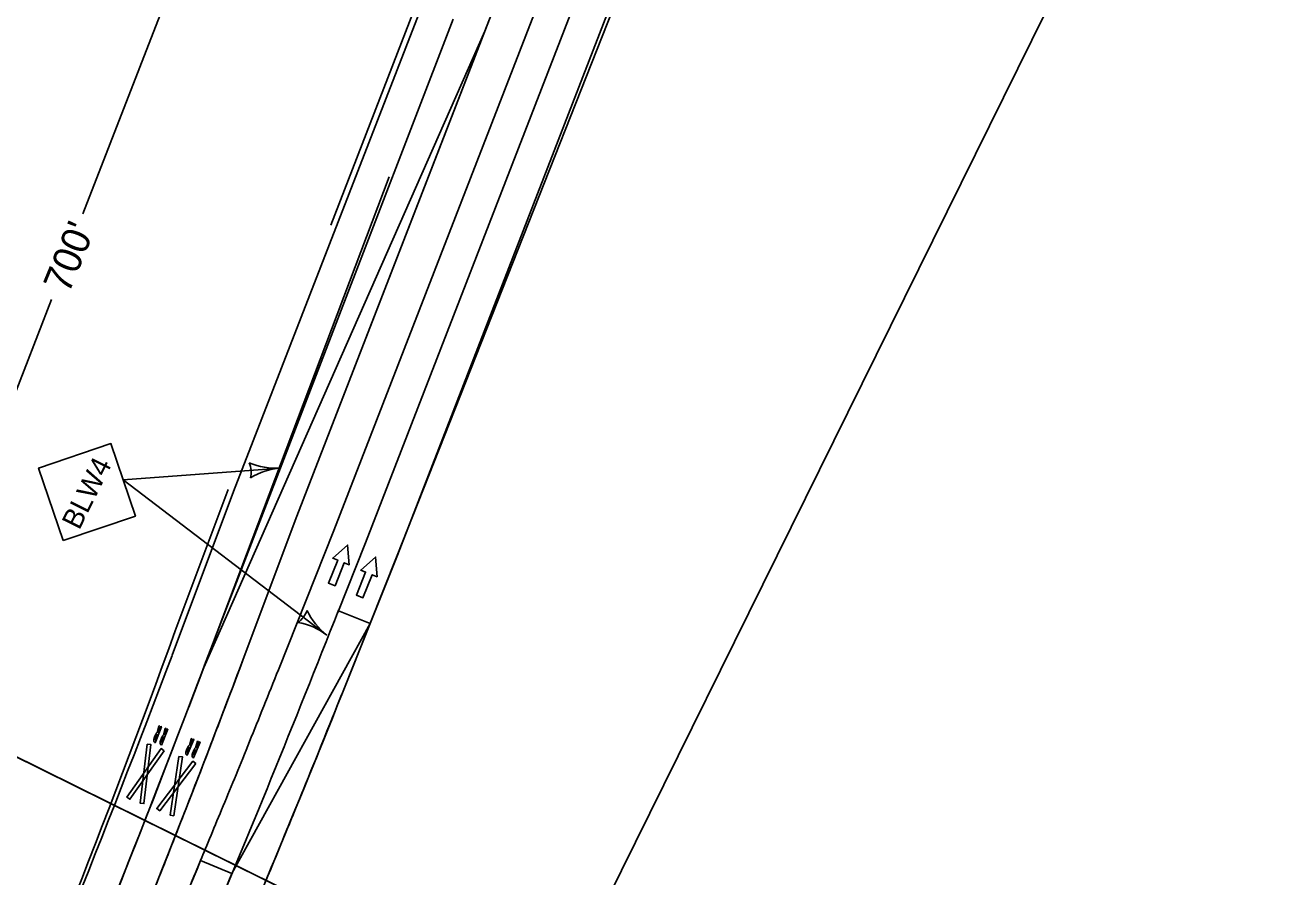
# Model space of a CAD drawing. Extents: x 14097936 to 14128734, y 8632000 to 8683104.
# Drawn here: x 14119789.7 to 14120235.7, y 8670080.4 to 8670380.8 of the extents above; entities that cross this region are included whole.
import ezdxf

# ---------------------------------------------------------------- set-up
doc = ezdxf.new("R2010")
doc.units = 0
for name, color, linetype in [('dsnNonPlotable', 7, 'Continuous'), ('dsnPaintExistingBrokenLaneLineWhite', 7, 'Continuous'), ('dsnPaintExistingEdgeLineRightWhite', 7, 'Continuous'), ('dsnPaintExistingNoPassingYellow', 7, 'Continuous'), ('dsnPaintPlaceBrokenLaneWhite', 7, 'Continuous'), ('dsnPaintPlaceNoPassingYellow', 7, 'Continuous'), ('dsnPaintRemoveChannelizingLaneYellow', 7, 'Continuous'), ('dsnShadingPaved', 7, 'Continuous'), ('dsnStdLabel', 7, 'Continuous'), ('dsnTapeRemoveChannelizingLaneWhite', 7, 'Continuous'), ('dsnTapeRemoveChannelizingLaneYellow', 7, 'Continuous'), ('Level 2', 7, 'Continuous'), ('Level 5', 7, 'Continuous'), ('trf_Cells1', 7, 'Continuous')]:
    doc.layers.add(name, color=color, linetype=linetype)

msp = doc.modelspace()

# ---------------------------------------------------------------- linework, layer by layer
at = {"layer": 'dsnNonPlotable'}
for points in [[(14119930.17, 8669941), (14120624.9, 8671346.14), (14120172.2, 8671569.96), (14119477.47, 8670164.82)], [(14118631.64, 8668945.1), (14119326.37, 8670350.23), (14120231.75, 8669902.59), (14119537.02, 8668497.46)], [(14119315.27, 8668607.09), (14120010, 8670012.23), (14119557.31, 8670236.05), (14118862.58, 8668830.91)]]:
    msp.add_lwpolyline(points, close=True, dxfattribs=at)
at = {"layer": 'dsnPaintExistingBrokenLaneLineWhite'}
for p, q in [((14119909.84, 8670198.21), (14120020.67, 8670484.12)), ((14119900.04, 8670173.67), (14119909.84, 8670198.21))]:
    msp.add_line(p, q, dxfattribs=at)
at = {"layer": 'dsnPaintExistingEdgeLineRightWhite'}
for p, q in [((14119972.19, 8670502.91), (14119897.54, 8670310.36)), ((14119920.98, 8670193.76), (14120033.72, 8670479.06)), ((14119861.35, 8670217.01), (14119842.61, 8670167.16)), ((14119901.38, 8670144.67), (14119920.98, 8670193.76))]:
    msp.add_line(p, q, dxfattribs=at)
for centre, radius, start, end in [((14116594.62, 8671342.65), 3454.16, 336.55764, 340.10427), ((14115455.27, 8671919.94), 4787.43, 334.8735, 338.23249)]:
    msp.add_arc(centre, radius, start, end, dxfattribs=at)
at = {"layer": 'dsnPaintExistingNoPassingYellow'}
for p, q in [((14119996.43, 8670493.52), (14119885.6, 8670207.61)), ((14119898.65, 8670202.55), (14120009.48, 8670488.46)), ((14119885.6, 8670207.61), (14119866.99, 8670158.14)), ((14119879.05, 8670153.47), (14119898.65, 8670202.55))]:
    msp.add_line(p, q, dxfattribs=at)
msp.add_arc((14115417.89, 8671831.2), 4753.27, 337.16763, 339.39146, dxfattribs=at)
at = {"layer": 'dsnPaintPlaceBrokenLaneWhite'}
msp.add_line((14119940.73, 8670383.04), (14119855.76, 8670162.36), dxfattribs=at)
for centre, radius, start, end in [((14115456.71, 8671919.32), 4773.86, 335.49481, 338.56158), ((14115416.69, 8671831.7), 4742.58, 334.09122, 339.391)]:
    msp.add_arc(centre, radius, start, end, dxfattribs=at)
at = {"layer": 'dsnPaintPlaceNoPassingYellow'}
msp.add_arc((14115456.71, 8671919.32), 4761.86, 334.13293, 337.35837, dxfattribs=at)
at = {"layer": 'dsnPaintRemoveChannelizingLaneYellow'}
msp.add_arc((14115570.48, 8671771.3), 4577.36, 336.80891, 339.3131, dxfattribs=at)
at = {"layer": 'dsnShadingPaved'}
for p, q in [((14119863.22, 8670216.29), (14119974.05, 8670502.19)), ((14119996.43, 8670493.52), (14119951.92, 8670378.71)), ((14119951.92, 8670378.71), (14119996.43, 8670493.52)), ((14119898.65, 8670202.55), (14120009.48, 8670488.46)), ((14120009.48, 8670488.46), (14119898.65, 8670202.55)), ((14119909.84, 8670198.21), (14120020.67, 8670484.12)), ((14120031.86, 8670479.78), (14119921.03, 8670193.88)), ((14119951.92, 8670378.71), (14119852.71, 8670154.3)), ((14119951.92, 8670378.71), (14119852.71, 8670154.3)), ((14119951.92, 8670378.71), (14119852.71, 8670154.3)), ((14119885.6, 8670207.61), (14119951.92, 8670378.71)), ((14119885.6, 8670207.61), (14119951.92, 8670378.71)), ((14119847.38, 8670140.26), (14119918.18, 8670327.31)), ((14119841.48, 8670158.54), (14119863.22, 8670216.29)), ((14119866.99, 8670158.14), (14119885.6, 8670207.61)), ((14119866.99, 8670158.14), (14119885.6, 8670207.61)), ((14119879.05, 8670153.47), (14119898.65, 8670202.55)), ((14119898.65, 8670202.55), (14119879.05, 8670153.47)), ((14119911.4, 8670169.76), (14119921.03, 8670193.88)), ((14119921.03, 8670193.88), (14119911.4, 8670169.76)), ((14119911.4, 8670169.76), (14119900.25, 8670174.21)), ((14119862.65, 8670081.54), (14119911.4, 8670169.76)), ((14119911.4, 8670169.76), (14119862.65, 8670081.54)), ((14119862.65, 8670081.54), (14119911.4, 8670169.76)), ((14119851.58, 8670086.16), (14119862.65, 8670081.54)), ((14119862.65, 8670081.54), (14119851.58, 8670086.16)), ((14119851.58, 8670086.16), (14119862.65, 8670081.54))]:
    msp.add_line(p, q, dxfattribs=at)
for points in [[(14119911.4, 8670169.76), (14119901.38, 8670144.67), (14119899.93, 8670141.07), (14119899.04, 8670138.84), (14119898.06, 8670136.41), (14119897.89, 8670135.99), (14119897.17, 8670134.2), (14119896.19, 8670131.75), (14119895.3, 8670129.55), (14119894.4, 8670127.31), (14119894.31, 8670127.08), (14119893.43, 8670124.9), (14119892.43, 8670122.42), (14119891.55, 8670120.26), (14119890.89, 8670118.63), (14119890.54, 8670117.75), (14119889.67, 8670115.61), (14119888.64, 8670113.09), (14119887.77, 8670110.96), (14119887.36, 8670109.96), (14119886.74, 8670108.43), (14119885.88, 8670106.32), (14119884.83, 8670103.77), (14119883.97, 8670101.68), (14119883.81, 8670101.29), (14119882.92, 8670099.11), (14119882.07, 8670097.05), (14119881, 8670094.46), (14119880.25, 8670092.64), (14119880.16, 8670092.41), (14119879.08, 8670089.81), (14119878.24, 8670087.78), (14119877.15, 8670085.17), (14119876.67, 8670084), (14119876.32, 8670083.15), (14119875.22, 8670080.52), (14119874.39, 8670078.53)], [(14119848.39, 8670078.55), (14119849.21, 8670080.5), (14119850.32, 8670083.15), (14119851.58, 8670086.16)], [(14119851.58, 8670086.16), (14119850.32, 8670083.15), (14119849.21, 8670080.5), (14119848.39, 8670078.55)]]:
    msp.add_lwpolyline(points, dxfattribs=at)
for radius, start in [(4565.36, 336.7987), (4577.36, 336.80891), (4577.36, 336.80891)]:
    msp.add_arc((14115570.48, 8671771.3), radius, start, 339.3131, dxfattribs=at)
for points in [[(14119789.07, 8669964), (14119790.92, 8669968.32), (14119796.39, 8669981.2), (14119805.42, 8670002.67), (14119816.06, 8670028.43), (14119826.56, 8670054.25), (14119836.9, 8670080.13), (14119847.09, 8670106.08), (14119857.14, 8670132.07), (14119863.71, 8670149.45), (14119866.99, 8670158.14)], [(14119789.07, 8669964), (14119790.92, 8669968.32), (14119796.39, 8669981.2), (14119805.42, 8670002.67), (14119816.06, 8670028.43), (14119826.56, 8670054.25), (14119836.9, 8670080.13), (14119847.09, 8670106.08), (14119857.14, 8670132.07), (14119863.71, 8670149.45), (14119866.99, 8670158.14)], [(14119851.58, 8670086.16), (14119853.73, 8670091.34), (14119859.45, 8670105.11), (14119868.64, 8670127.53), (14119875.58, 8670144.82), (14119879.05, 8670153.47)], [(14119879.05, 8670153.47), (14119875.58, 8670144.82), (14119868.64, 8670127.53), (14119859.45, 8670105.11), (14119853.73, 8670091.34), (14119851.58, 8670086.16)]]:
    msp.add_open_spline(points, degree=3, dxfattribs=at)
at = {"layer": 'dsnStdLabel'}
for p, q in [((14119810.02, 8670314.3), (14119929.02, 8670621.21)), ((14119765.11, 8670196.89), (14119798.91, 8670284.08)), ((14119879.73, 8670224.61), (14119824.26, 8670220.46)), ((14119896.13, 8670165.71), (14119824.26, 8670220.46))]:
    msp.add_line(p, q, dxfattribs=at)
msp.add_lwpolyline([(14119803.01, 8670199.02), (14119828.58, 8670207.67), (14119819.93, 8670233.25), (14119794.35, 8670224.6)], close=True, dxfattribs=at)
for centre, radius, start, end in [((14119878.02, 8670247.49), 22.95, 246.2011, 274.2724), ((14119860.54, 8670223.17), 8.86, 346.5381, 22.0066), ((14119881.44, 8670201.72), 22.95, 94.2723, 122.3435), ((14119880.83, 8670177.37), 8.86, 304.9652, 340.4336), ((14119910.04, 8670183.96), 22.95, 204.6282, 232.6995), ((14119882.23, 8670147.45), 22.95, 52.6993, 80.7706)]:
    msp.add_arc(centre, radius, start, end, dxfattribs=at)
at = {"layer": 'dsnTapeRemoveChannelizingLaneWhite'}
msp.add_line((14119862.65, 8670081.54), (14119911.4, 8670169.76), dxfattribs=at)
msp.add_arc((14118559.34, 8670625.19), 1412.15, 319.58068, 337.35767, dxfattribs=at)
at = {"layer": 'dsnTapeRemoveChannelizingLaneYellow'}
msp.add_line((14119951.92, 8670378.71), (14119852.71, 8670154.3), dxfattribs=at)
msp.add_arc((14118559.34, 8670625.19), 1400.15, 321.68516, 337.35766, dxfattribs=at)
at = {"layer": 'Level 2'}
for points in [[(14119896.72, 8670184), (14119899.04, 8670183.07), (14119902.29, 8670191.2), (14119904.03, 8670190.5), (14119903.46, 8670197.46), (14119898.23, 8670192.82), (14119899.97, 8670192.13)], [(14119906.58, 8670179.77), (14119908.9, 8670178.84), (14119912.16, 8670186.96), (14119913.9, 8670186.26), (14119913.32, 8670193.23), (14119908.1, 8670188.59), (14119909.84, 8670187.89)]]:
    msp.add_lwpolyline(points, close=True, dxfattribs=at)
at = {"layer": 'Level 5'}
for points in [[(14119899.97, 8670192.13), (14119898.23, 8670192.82), (14119903.46, 8670197.46), (14119904.03, 8670190.5), (14119902.29, 8670191.2), (14119899.04, 8670183.07), (14119896.72, 8670184), (14119899.97, 8670192.13)], [(14119909.84, 8670187.89), (14119908.1, 8670188.59), (14119913.32, 8670193.23), (14119913.9, 8670186.26), (14119912.16, 8670186.96), (14119908.9, 8670178.84), (14119906.58, 8670179.77), (14119909.84, 8670187.89)]]:
    msp.add_lwpolyline(points, dxfattribs=at)
at = {"layer": 'trf_Cells1'}
for p, q in [((14119835.46, 8670130.07), (14119835.29, 8670129.62)), ((14119835.7, 8670128.69), (14119836.39, 8670130.49)), ((14119837.7, 8670129.21), (14119837.53, 8670128.76)), ((14119837.94, 8670127.83), (14119838.63, 8670129.63)), ((14119846.8, 8670125.65), (14119846.61, 8670125.21)), ((14119847, 8670124.27), (14119847.75, 8670126.04)), ((14119849.01, 8670124.72), (14119848.82, 8670124.27)), ((14119849.21, 8670123.33), (14119849.96, 8670125.1))]:
    msp.add_line(p, q, dxfattribs=at)
for points in [[(14119836.46, 8670131.4), (14119837.06, 8670133.57), (14119836.84, 8670133.66), (14119836.21, 8670131.3)], [(14119835.58, 8670127.71), (14119837.73, 8670133.31), (14119837.51, 8670133.4), (14119836.73, 8670131.38)], [(14119837.82, 8670126.85), (14119839.97, 8670132.45), (14119839.75, 8670132.54), (14119838.97, 8670130.52)], [(14119838.7, 8670130.54), (14119839.3, 8670132.71), (14119839.08, 8670132.8), (14119838.45, 8670130.44)], [(14119847.85, 8670126.95), (14119848.52, 8670129.09), (14119848.3, 8670129.19), (14119847.6, 8670126.86)], [(14119846.84, 8670123.29), (14119849.19, 8670128.81), (14119848.97, 8670128.91), (14119848.12, 8670126.92)], [(14119849.05, 8670122.35), (14119851.4, 8670127.88), (14119851.17, 8670127.97), (14119850.33, 8670125.98)], [(14119850.06, 8670126.01), (14119850.73, 8670128.16), (14119850.51, 8670128.25), (14119849.8, 8670125.92)]]:
    msp.add_lwpolyline(points, dxfattribs=at)
for points in [[(14119838.75, 8670124.89), (14119826.6, 8670107.77), (14119825.52, 8670108.55), (14119837.66, 8670125.66)], [(14119832.68, 8670127.22), (14119830.26, 8670106.37), (14119831.58, 8670106.22), (14119834.01, 8670127.06)], [(14119849.91, 8670120.36), (14119837.17, 8670103.68), (14119836.11, 8670104.49), (14119848.85, 8670121.17)], [(14119843.93, 8670122.9), (14119840.78, 8670102.15), (14119842.1, 8670101.95), (14119845.24, 8670122.7)]]:
    msp.add_lwpolyline(points, close=True, dxfattribs=at)
for points in [[(14119835.29, 8670129.62), (14119835.15, 8670129.25), (14119835.11, 8670129.07), (14119835.08, 8670128.92), (14119835.06, 8670128.77), (14119835.05, 8670128.65), (14119835.05, 8670128.48), (14119835.06, 8670128.37), (14119835.08, 8670128.27), (14119835.1, 8670128.19), (14119835.14, 8670128.08), (14119835.17, 8670128.02), (14119835.22, 8670127.96), (14119835.26, 8670127.91), (14119835.32, 8670127.85), (14119835.37, 8670127.82), (14119835.44, 8670127.78), (14119835.58, 8670127.71)], [(14119835.6, 8670129.76), (14119835.55, 8670129.64), (14119835.51, 8670129.52), (14119835.48, 8670129.41), (14119835.45, 8670129.26), (14119835.45, 8670129.18), (14119835.44, 8670129.09), (14119835.45, 8670129.02), (14119835.46, 8670128.96), (14119835.49, 8670128.89), (14119835.53, 8670128.83), (14119835.57, 8670128.78), (14119835.63, 8670128.74), (14119835.7, 8670128.69)], [(14119836.21, 8670131.3), (14119836.17, 8670131.28), (14119836.09, 8670131.21), (14119836, 8670131.11), (14119835.95, 8670131.04), (14119835.88, 8670130.93), (14119835.81, 8670130.82), (14119835.77, 8670130.75), (14119835.71, 8670130.63), (14119835.64, 8670130.5), (14119835.6, 8670130.41), (14119835.55, 8670130.29), (14119835.46, 8670130.07)], [(14119836.39, 8670130.49), (14119836.31, 8670130.5), (14119836.24, 8670130.51), (14119836.17, 8670130.5), (14119836.1, 8670130.48), (14119836.04, 8670130.45), (14119835.98, 8670130.41), (14119835.93, 8670130.36), (14119835.87, 8670130.29), (14119835.83, 8670130.23), (14119835.75, 8670130.1), (14119835.69, 8670129.99), (14119835.65, 8670129.89), (14119835.6, 8670129.76)], [(14119836.73, 8670131.38), (14119836.64, 8670131.4), (14119836.53, 8670131.41), (14119836.46, 8670131.4)], [(14119838.45, 8670130.44), (14119838.41, 8670130.42), (14119838.33, 8670130.35), (14119838.24, 8670130.25), (14119838.19, 8670130.18), (14119838.12, 8670130.07), (14119838.05, 8670129.96), (14119838.01, 8670129.89), (14119837.95, 8670129.77), (14119837.88, 8670129.64), (14119837.84, 8670129.55), (14119837.79, 8670129.43), (14119837.7, 8670129.21)], [(14119838.63, 8670129.63), (14119838.55, 8670129.64), (14119838.48, 8670129.65), (14119838.41, 8670129.64), (14119838.35, 8670129.62), (14119838.28, 8670129.59), (14119838.22, 8670129.55), (14119838.17, 8670129.5), (14119838.11, 8670129.43), (14119838.07, 8670129.37), (14119837.99, 8670129.24), (14119837.93, 8670129.13), (14119837.89, 8670129.03), (14119837.84, 8670128.9)], [(14119838.97, 8670130.52), (14119838.88, 8670130.54), (14119838.77, 8670130.55), (14119838.7, 8670130.54)], [(14119837.53, 8670128.76), (14119837.39, 8670128.39), (14119837.35, 8670128.21), (14119837.32, 8670128.06), (14119837.3, 8670127.91), (14119837.29, 8670127.79), (14119837.29, 8670127.62), (14119837.3, 8670127.51), (14119837.32, 8670127.41), (14119837.34, 8670127.33), (14119837.38, 8670127.22), (14119837.41, 8670127.16), (14119837.46, 8670127.1), (14119837.5, 8670127.05), (14119837.56, 8670126.99), (14119837.61, 8670126.96), (14119837.68, 8670126.92), (14119837.82, 8670126.85)], [(14119837.84, 8670128.9), (14119837.79, 8670128.78), (14119837.75, 8670128.66), (14119837.72, 8670128.55), (14119837.69, 8670128.4), (14119837.69, 8670128.32), (14119837.68, 8670128.23), (14119837.69, 8670128.16), (14119837.7, 8670128.1), (14119837.73, 8670128.03), (14119837.77, 8670127.97), (14119837.81, 8670127.92), (14119837.87, 8670127.88), (14119837.94, 8670127.83)], [(14119846.61, 8670125.21), (14119846.47, 8670124.84), (14119846.41, 8670124.66), (14119846.38, 8670124.51), (14119846.35, 8670124.37), (14119846.34, 8670124.25), (14119846.33, 8670124.08), (14119846.34, 8670123.97), (14119846.36, 8670123.86), (14119846.38, 8670123.78), (14119846.42, 8670123.67), (14119846.44, 8670123.62), (14119846.49, 8670123.55), (14119846.53, 8670123.5), (14119846.59, 8670123.44), (14119846.63, 8670123.4), (14119846.7, 8670123.36), (14119846.84, 8670123.29)], [(14119846.93, 8670125.34), (14119846.88, 8670125.22), (14119846.84, 8670125.11), (14119846.8, 8670124.99), (14119846.76, 8670124.84), (14119846.76, 8670124.76), (14119846.75, 8670124.67), (14119846.75, 8670124.61), (14119846.77, 8670124.54), (14119846.79, 8670124.47), (14119846.83, 8670124.41), (14119846.87, 8670124.36), (14119846.93, 8670124.31), (14119847, 8670124.27)], [(14119847.6, 8670126.86), (14119847.56, 8670126.83), (14119847.47, 8670126.77), (14119847.38, 8670126.67), (14119847.33, 8670126.61), (14119847.25, 8670126.5), (14119847.18, 8670126.39), (14119847.14, 8670126.32), (14119847.07, 8670126.2), (14119847, 8670126.07), (14119846.95, 8670125.98), (14119846.9, 8670125.86), (14119846.8, 8670125.65)], [(14119847.75, 8670126.04), (14119847.67, 8670126.05), (14119847.59, 8670126.06), (14119847.53, 8670126.06), (14119847.46, 8670126.04), (14119847.39, 8670126.01), (14119847.33, 8670125.97), (14119847.28, 8670125.93), (14119847.22, 8670125.86), (14119847.17, 8670125.8), (14119847.09, 8670125.68), (14119847.03, 8670125.57), (14119846.98, 8670125.46), (14119846.93, 8670125.34)], [(14119848.12, 8670126.92), (14119848.03, 8670126.94), (14119847.92, 8670126.95), (14119847.85, 8670126.95)], [(14119849.8, 8670125.92), (14119849.77, 8670125.9), (14119849.68, 8670125.83), (14119849.59, 8670125.73), (14119849.54, 8670125.67), (14119849.46, 8670125.56), (14119849.39, 8670125.46), (14119849.35, 8670125.38), (14119849.28, 8670125.26), (14119849.21, 8670125.13), (14119849.16, 8670125.05), (14119849.11, 8670124.93), (14119849.01, 8670124.72)], [(14119849.96, 8670125.1), (14119849.88, 8670125.12), (14119849.8, 8670125.12), (14119849.74, 8670125.12), (14119849.67, 8670125.1), (14119849.6, 8670125.07), (14119849.54, 8670125.04), (14119849.49, 8670124.99), (14119849.43, 8670124.92), (14119849.38, 8670124.87), (14119849.3, 8670124.74), (14119849.24, 8670124.63), (14119849.19, 8670124.52), (14119849.14, 8670124.4)], [(14119850.33, 8670125.98), (14119850.24, 8670126.01), (14119850.13, 8670126.01), (14119850.06, 8670126.01)], [(14119848.82, 8670124.27), (14119848.67, 8670123.9), (14119848.62, 8670123.72), (14119848.59, 8670123.57), (14119848.56, 8670123.43), (14119848.55, 8670123.31), (14119848.54, 8670123.14), (14119848.55, 8670123.03), (14119848.56, 8670122.92), (14119848.59, 8670122.85), (14119848.62, 8670122.74), (14119848.65, 8670122.68), (14119848.7, 8670122.61), (14119848.74, 8670122.56), (14119848.79, 8670122.5), (14119848.84, 8670122.47), (14119848.91, 8670122.42), (14119849.05, 8670122.35)], [(14119849.14, 8670124.4), (14119849.09, 8670124.28), (14119849.04, 8670124.17), (14119849.01, 8670124.05), (14119848.97, 8670123.9), (14119848.97, 8670123.83), (14119848.96, 8670123.74), (14119848.96, 8670123.67), (14119848.97, 8670123.6), (14119849, 8670123.53), (14119849.04, 8670123.47), (14119849.08, 8670123.42), (14119849.14, 8670123.37), (14119849.21, 8670123.33)]]:
    msp.add_spline(points, degree=3, dxfattribs=at)

# ---------------------------------------------------------------- texts
at = {"layer": 'dsnStdLabel'}
for s, height, rotation, p in [("700'", 10, 67.6002, (14119804.98, 8670285.81)), ('BLW4', 7.2, 63.6912, (14119808.73, 8670202.48))]:
    msp.add_text(s, height=height, rotation=rotation, dxfattribs=at).set_placement(p)

doc.saveas('drawing.dxf')
